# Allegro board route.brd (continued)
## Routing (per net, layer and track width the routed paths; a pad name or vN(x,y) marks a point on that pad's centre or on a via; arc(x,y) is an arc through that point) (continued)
UNNAMED_1_CON40P_I55_A_15: length 15.8
  TOP w0.15: D53.2 20.77,30.22 21.27,30.72 21.64,30.72 22.84,31.92 22.84,33.12 28.03,38.31 28.03,39.82 28.81,40.6 28.81,40.78 J3.15
UNNAMED_1_CON40P_I55_A_16: length 18.1
  TOP w0.15: D59.2 20.77,16.84 21.8,15.81 24.72,15.81 27.08,18.17 27.08,24.85 28.47,26.24 J3.3
UNNAMED_1_CON40P_I55_A_17: length 23.1
  TOP w0.15: J3.4 30.94,25.14 28.37,25.14 27.6,24.37 27.6,18.18 24.87,15.45 19.66,15.45 18.27,16.84 D59.1
UNNAMED_1_CON40P_I55_A_18: length 24.6
  TOP w0.15: J3.20 30.76,45.28 28.9,45.28 27,43.38 27,43.17 26.95,43.12 26.95,38.75 22.52,34.32 22.08,34.32 21.76,34 21.76,32.37 21.19,31.8 19.29,31.8 18.27,32.82 D51.1
UNNAMED_1_CON40P_I55_A_19: length 17.3
  TOP w0.15: D51.2 20.77,34.22 21.23,34.68 22.37,34.68 26.59,38.9 26.59,43.27 26.64,43.32 26.64,43.7 J3.19
UNNAMED_1_CON40P_I55_A_20: length 29.8
  TOP w0.15: J3.26 30.93,53.07 29.54,53.07 27.84,51.37 27.84,49.82 27.51,49.49 27.51,49.12 24.84,46.45 24.84,44.06 24.79,44.01 24.79,41.35 22.82,39.38 15.22,39.38 13.77,40.82 D48.1
UNNAMED_1_CON40P_I55_A_21: length 24.8
  TOP w0.15: D48.2 16.27,40.82 17.36,39.74 22.67,39.74 24.43,41.5 24.43,44.16 24.48,44.21 24.48,46.6 27.15,49.27 27.15,49.64 27.48,49.97 27.48,52.16 J3.25
UNNAMED_1_CON40P_I55_A_22: length 25.7
  TOP w0.15: D49.1 18.27,36.82 19.3,35.79 21.95,35.79 25.51,39.35 25.51,43.72 25.56,43.77 25.56,46.16 28.23,48.83 28.23,49.19 28.56,49.52 28.56,49.55 29.34,50.33 30.73,50.33 J3.24
UNNAMED_1_CON40P_I55_A_23: length 18.6
  TOP w0.15: J3.23 28.81,50.95 28.81,50.31 28.2,49.7 28.2,49.67 27.87,49.34 27.87,48.98 25.2,46.31 25.2,43.91 25.15,43.86 25.15,41.2 22.83,38.88 21.43,38.88 20.77,38.22 D49.2
UNNAMED_1_CON40P_I55_A_24: length 29.2
  TOP w0.15: D50.1 13.77,36.82 15.55,35.04 22.22,35.04 26.23,39.05 26.23,43.42 26.28,43.47 26.28,45.28 28.93,47.93 30.87,47.93 J3.22
UNNAMED_1_CON40P_I55_A_25: length 23.9
  TOP w0.15: D50.2 16.27,36.82 17.69,35.4 22.07,35.4 25.87,39.2 25.87,43.57 25.92,43.62 25.92,45.52 J3.21
UNNAMED_1_CON40P_I55_A_26: length 26.6
  TOP w0.15: J3.28 30.84,55.52 29.45,55.52 26.79,52.86 26.79,49.42 24.12,46.75 24.12,44.36 24.05,44.29 24.05,41.63 22.52,40.1 19,40.1 18.27,40.82 D47.1
UNNAMED_1_CON40P_I55_A_27: length 19.2
  TOP w0.15: D47.2 20.77,42.22 21.43,42.88 22.13,42.88 23.76,44.51 23.76,46.9 26.43,49.57 26.43,53.65 J3.27
UNNAMED_1_CON40P_I55_A_28: length 20.9
  TOP w0.15: D60.2 16.27,16.84 18.02,15.09 25.49,15.09 29.5,19.1 J3.1
UNNAMED_1_CON40P_I55_A_29: length 25.6
  TOP w0.15: J3.2 32.04,20.29 26.48,14.73 15.88,14.73 13.77,16.84 D60.1
UNNAMED_1_CON40P_I55_A_30: length 24.2
  TOP w0.15: D45.1 13.77,53.75 15.38,52.14 22.02,52.14 27.75,57.87 27.75,58.9 29.37,60.52 30.76,60.52 J3.32
UNNAMED_1_CON40P_I55_A_31: length 19.3
  TOP w0.15: J3.31 27.82,60.12 27.82,59.49 27.39,59.06 27.39,58.02 21.87,52.5 17.52,52.5 16.27,53.75 D45.2
UNNAMED_1_CON40P_I55_A_32: length 21.5
  TOP w0.15: J3.35 28.81,66.19 28.42,66.19 26.45,64.21 26.45,60.85 26.38,60.78 26.38,60.08 22.71,56.41 17.25,56.41 16.01,57.65 D43.2
UNNAMED_1_CON40P_I55_A_33: length 26.6
  TOP w0.15: D43.1 13.94,58.45 16.34,56.05 22.86,56.05 26.74,59.93 26.74,60.63 26.81,60.7 26.81,64.07 28.46,65.71 30.87,65.71 J3.36
UNNAMED_1_CON40P_I55_A_34: length 21.3
  TOP w0.15: J3.34 31.01,63.31 29.14,63.31 27.53,61.7 27.53,60.41 27.46,60.34 27.46,59.63 27.03,59.2 27.03,58.17 21.84,52.98 19.04,52.98 18.27,53.75 D44.1
UNNAMED_1_CON40P_I55_A_35: length 14.5
  TOP w0.15: J3.33 27.17,62.01 27.17,60.55 27.1,60.48 27.1,59.78 23.01,55.69 21.31,55.69 20.77,55.15 D44.2
UNNAMED_1_CON40P_I55_A_36: length 22.9
  TOP w0.15: D52.2 16.27,32.72 17.55,31.44 21.34,31.44 22.12,32.22 22.12,33.42 27.31,38.61 27.31,42.82 28.52,44.02 J3.17
UNNAMED_1_CON40P_I55_A_37: length 22.8
  TOP w0.15: J3.38 30.49,67.87 29.1,67.87 28.52,67.29 28.52,66.79 26.09,64.36 26.09,61 26.02,60.93 26.02,60.23 22.56,56.77 19.25,56.77 18.27,57.75 D42.1
UNNAMED_1_CON40P_I55_A_38: length 16
  TOP w0.15: J3.37 29.5,68.44 29.29,68.23 28.95,68.23 28.16,67.44 28.16,66.94 25.73,64.51 25.73,61.3 22.88,58.45 D42.2
UNNAMED_1_CON40P_I55_A_39: length 27.5
  TOP w0.15: D52.1 14.2,33.52 16.64,31.08 21.49,31.08 22.48,32.07 22.48,33.27 27.67,38.46 27.67,39.97 28.16,40.46 28.16,42.26 28.56,42.66 30.68,42.66 J3.18

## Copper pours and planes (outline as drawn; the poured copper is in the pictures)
GND on BOTTOM: 7.46,7.64 7.46,181.64 37.46,181.64 37.46,7.64 18.77,7.64 18.77,9.43 15.87,9.43 15.87,7.64
(no net) on TOP: 7.46,7.64 7.46,181.64 37.46,181.64 37.46,7.64 18.77,7.64 18.77,9.43 15.9,9.43 15.87,9.4 15.87,7.64 ; 70 cut-outs
Net_2 on TOP (solid shape): outline of 114 points within 23.14,73.84 35.14,83.84
Net_3 on TOP (solid shape): outline of 114 points within 23.24,84.52 35.24,94.52
Net_4 on TOP (solid shape): outline of 114 points within 23.24,95.1 35.24,105.1
Net_5 on TOP (solid shape): outline of 114 points within 8.48,135.46 20.48,145.46
Net_62 on TOP (solid shape): outline of 114 points within 8.43,124.59 20.43,134.59
Net_62 on TOP (solid shape): outline of 114 points within 23.24,105.59 35.24,117.59

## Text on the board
BOTTOM: 2
TOP: 1
DISPLAY_TOP: TETE_LED2019_COTE_ELEMENTS
DEVICE_TYPE_TOP: TETE_LED2018_COTE_SOUDURES
FILM_CABTOP: TETE_LED2019_PLAN_CABLAGE_ELEMENTS
User.5: TETE_LED2019_PLAN_CABLAGE_SOUDURES
User.6: TETE_LED_2019 | DICE LPNHE | 04/2019 | TETE_LED2019_SERIGRAPHIE_ELEMENTS
User.7: 04/2019 | DICE LPNHE | TETE_LED_2019 | TETE_LED2019_SERIGRAPHIE_SOUDURES
User.8: TETE_LED2019_VERNIS_EPARGNE_ELEMENTS
User.9: TETE_LED2019_VERNIS_EPARGNE_SOUDURES
User.10: TETE_LED2019_PLAGES_SOUDURES_ELEMENTS
User.12: TETE_LED2019_DIMENSIONS
User.13: TETE_LED2019_PLAN_PERCAGE
User.15: FIGURE | FINISHED_SIZE | 0.3 | 1.0 | 3.2 | DRILL CHART: TOP to BOTTOM | ALL UNITS ARE IN MILLIMETERS | PLATED | QTY | 107 | 120 | 4 | 231 | TOTAL HOLES:
